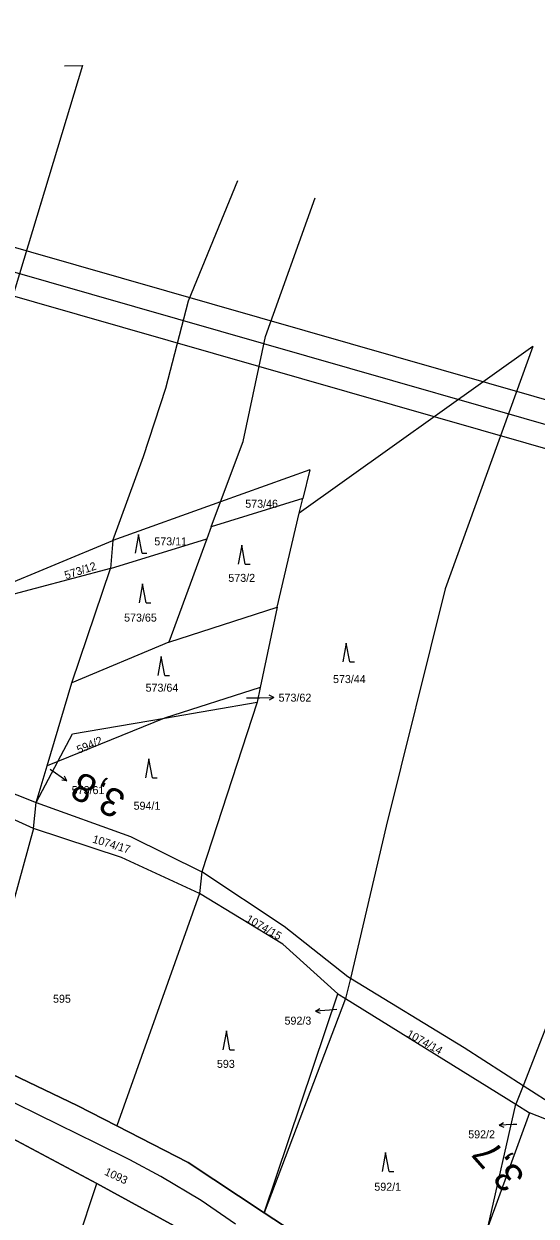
# Model space of a CAD drawing. Extents: x -738085 to -734306, y -1122197 to -1119753.
# Drawn here: x -736902.9 to -736794, y -1121585.1 to -1121331.9 of the extents above; entities that cross this region are included whole.
import ezdxf

# ---------------------------------------------------------------- set-up
doc = ezdxf.new("R2010")
doc.units = 0
for name, color, linetype in [('Hranice parcel', 7, 'Continuous'), ('Parcelní čísla', 7, 'Continuous'), ('Pop  PČ popisy', 7, 'Continuous'), ('SŽDC', 7, 'Continuous'), ('Vrstva 1', 7, 'Continuous'), ('Vrstva 53', 7, 'Continuous'), ('Vrstva 7', 7, 'Continuous'), ('Značky kultur', 7, 'Continuous')]:
    doc.layers.add(name, color=color, linetype=linetype)

msp = doc.modelspace()

# ---------------------------------------------------------------- linework, layer by layer
at = {"layer": 'Hranice parcel'}
for p, q in [((-736794.71, -1121400.41), (-736844.34, -1121435.79)), ((-736842.12, -1121426.59), (-736861.06, -1121433.39)), ((-736842.12, -1121426.59), (-736843.6, -1121432.65)), ((-736861.06, -1121433.39), (-736884.01, -1121441.6)), ((-736843.6, -1121432.65), (-736863.05, -1121438.7)), ((-736863.05, -1121438.7), (-736861.06, -1121433.39)), ((-736844.34, -1121435.79), (-736843.6, -1121432.65)), ((-736849.05, -1121455.75), (-736844.34, -1121435.79)), ((-736863.05, -1121438.7), (-736863.97, -1121441.2)), ((-736884.5, -1121447.55), (-736863.97, -1121441.2)), ((-736863.97, -1121441.2), (-736872.05, -1121463.15)), ((-736922.28, -1121457.48), (-736884.01, -1121441.6)), ((-736884.01, -1121441.6), (-736884.5, -1121447.55)), ((-736884.5, -1121447.55), (-736922.28, -1121457.48)), ((-736892.67, -1121471.82), (-736884.5, -1121447.55)), ((-736872.05, -1121463.15), (-736849.05, -1121455.75)), ((-736849.05, -1121455.75), (-736852.65, -1121472.82)), ((-736872.05, -1121463.15), (-736892.67, -1121471.82)), ((-736897.97, -1121489.45), (-736892.67, -1121471.82)), ((-736852.65, -1121472.82), (-736873.01, -1121479.3)), ((-736852.65, -1121472.82), (-736853.31, -1121475.93)), ((-736873.01, -1121479.3), (-736853.31, -1121475.93)), ((-736853.31, -1121475.93), (-736865.09, -1121511.93)), ((-736873.01, -1121479.3), (-736895.68, -1121488.52)), ((-736921.65, -1121488.79), (-736900.3, -1121497.21)), ((-736900.3, -1121497.21), (-736895.68, -1121488.52)), ((-736895.68, -1121488.52), (-736897.97, -1121489.45)), ((-736900.3, -1121497.21), (-736897.97, -1121489.45)), ((-736900.82, -1121502.75), (-736922.19, -1121493.03)), ((-736900.82, -1121502.75), (-736900.3, -1121497.21)), ((-736900.82, -1121502.75), (-736914.25, -1121550.72)), ((-736865.09, -1121511.93), (-736865.57, -1121516.55)), ((-736865.57, -1121516.55), (-736883.17, -1121565.89)), ((-736833.47, -1121534.61), (-736834.53, -1121538.84)), ((-736833.47, -1121534.61), (-736834.05, -1121534.26)), ((-736851.83, -1121584.35), (-736836.13, -1121537.85)), ((-736834.53, -1121538.84), (-736851.83, -1121584.35)), ((-736836.13, -1121537.85), (-736834.53, -1121538.84)), ((-736834.53, -1121538.84), (-736798.31, -1121561.29)), ((-736796.78, -1121557.37), (-736798.31, -1121561.29)), ((-736916.19, -1121562.83), (-736887.39, -1121578.1)), ((-736804.2, -1121587.16), (-736798.31, -1121561.29)), ((-736798.31, -1121561.29), (-736795.38, -1121563.11)), ((-736795.38, -1121563.11), (-736804.2, -1121587.16)), ((-736883.17, -1121565.89), (-736867.94, -1121573.69)), ((-736867.94, -1121573.69), (-736851.83, -1121584.35)), ((-736920.64, -1121677.71), (-736887.39, -1121578.1)), ((-736887.39, -1121578.1), (-736870.91, -1121587.14))]:
    msp.add_line(p, q, dxfattribs=at)
for points in [[(-736894.23, -1121340.75), (-736890.46, -1121340.68), (-736908.31, -1121399.47), (-736915.28, -1121436.76), (-736922.28, -1121457.48)], [(-736884.01, -1121441.6), (-736877.47, -1121423.75), (-736872.69, -1121409.19), (-736867.93, -1121390.68), (-736857.42, -1121365.14)], [(-736861.06, -1121433.39), (-736856.25, -1121420.58), (-736851.5, -1121398.27), (-736840.95, -1121368.78)], [(-736794.71, -1121400.41), (-736813.35, -1121451.81), (-736825.88, -1121502.26), (-736833.47, -1121534.61)], [(-736759.54, -1121449.86), (-736767.29, -1121474.26), (-736779.34, -1121512.65), (-736796.78, -1121557.37)], [(-736895.68, -1121488.52), (-736892.56, -1121482.65), (-736873.01, -1121479.3)], [(-736900.3, -1121497.21), (-736880.2, -1121504.4), (-736865.09, -1121511.93)], [(-736865.57, -1121516.55), (-736882.16, -1121508.87), (-736900.82, -1121502.75)], [(-736834.05, -1121534.26), (-736847.54, -1121523.54), (-736865.09, -1121511.93)], [(-736836.13, -1121537.85), (-736847.84, -1121527.31), (-736865.57, -1121516.55)], [(-736796.78, -1121557.37), (-736809.3, -1121549.29), (-736833.47, -1121534.61)], [(-736914.25, -1121550.72), (-736891.6, -1121561.57), (-736883.17, -1121565.89)], [(-736779.28, -1121565.27), (-736789.46, -1121562.09), (-736796.78, -1121557.37)], [(-736780.39, -1121568.35), (-736787.24, -1121566.27), (-736795.38, -1121563.11)], [(-736816.01, -1121619.92), (-736826.87, -1121606.1), (-736845.88, -1121588.28), (-736851.83, -1121584.35)]]:
    msp.add_lwpolyline(points, dxfattribs=at)
at = {"layer": 'Pop  PČ popisy'}
for p, q in [((-736855.58, -1121475.01), (-736852.74, -1121474.98)), ((-736852.74, -1121474.98), (-736849.74, -1121474.93)), ((-736849.74, -1121474.93), (-736850.75, -1121474.44)), ((-736849.74, -1121474.93), (-736850.73, -1121475.45)), ((-736897.3, -1121490.14), (-736896.2, -1121490.9)), ((-736896.2, -1121490.9), (-736893.74, -1121492.62)), ((-736893.74, -1121492.62), (-736894.28, -1121491.64)), ((-736893.74, -1121492.62), (-736894.85, -1121492.46)), ((-736840.93, -1121541.56), (-736839.98, -1121540.98)), ((-736837.94, -1121541.3), (-736840.93, -1121541.56)), ((-736840.93, -1121541.56), (-736839.89, -1121541.97)), ((-736836.39, -1121541.17), (-736837.94, -1121541.3)), ((-736801.88, -1121565.71), (-736800.9, -1121565.17)), ((-736798.88, -1121565.6), (-736801.88, -1121565.71)), ((-736801.88, -1121565.71), (-736800.86, -1121566.17)), ((-736798.12, -1121565.57), (-736798.88, -1121565.6))]:
    msp.add_line(p, q, dxfattribs=at)
at = {"layer": 'SŽDC'}
for p, q in [((-736916.19, -1121562.83), (-736887.39, -1121578.1)), ((-736867.94, -1121573.69), (-736883.17, -1121565.89)), ((-736851.83, -1121584.35), (-736867.94, -1121573.69)), ((-736887.39, -1121578.1), (-736870.91, -1121587.14))]:
    msp.add_line(p, q, dxfattribs=at)
for points in [[(-736883.17, -1121565.89), (-736891.6, -1121561.57), (-736914.25, -1121550.72)], [(-736816.01, -1121619.92), (-736826.87, -1121606.1), (-736845.88, -1121588.28), (-736851.83, -1121584.35)]]:
    msp.add_lwpolyline(points, dxfattribs=at)
at = {"layer": 'Vrstva 1'}
for points in [[(-736726.43, -1121430.48), (-737533.93, -1121199.12), (-737615.73, -1121484.62), (-736808.23, -1121715.98)], [(-737530.5, -1121205.3), (-736732.61, -1121433.9), (-736811.65, -1121709.79), (-737609.54, -1121481.19)], [(-736738.79, -1121437.33), (-737330, -1121267.94), (-737406.29, -1121534.23), (-736815.08, -1121703.62)]]:
    msp.add_lwpolyline(points, close=True, dxfattribs=at)
msp.add_lwpolyline([(-736857.9, -1121586.77), (-736865.18, -1121581.77), (-736873.79, -1121576.65), (-736880.36, -1121573.13), (-736887.36, -1121569.62), (-736895.47, -1121565.67), (-736909.09, -1121558.99), (-736915.79, -1121555.68), (-736924.59, -1121551.29), (-736931.47, -1121547.72), (-736939.01, -1121543.72), (-736944.31, -1121540.84), (-736948.04, -1121538.79), (-736964.17, -1121529.72), (-736980.55, -1121520.47)], dxfattribs=at)
at = {"layer": 'Vrstva 53'}
for points in [[(-736870.91, -1121587.14), (-736887.39, -1121578.1), (-736916.19, -1121562.83), (-736926.41, -1121557.42), (-736946.26, -1121546.1), (-736963.67, -1121535.61), (-736980.18, -1121525.56), (-736982.11, -1121524.39), (-736990.76, -1121519.12), (-737010.34, -1121510.73), (-737043.34, -1121491.76), (-737040.45, -1121481.52)], [(-737040.45, -1121481.52), (-737004.89, -1121500.61), (-736987.4, -1121511.36), (-736979.67, -1121517.22), (-736979.36, -1121517.39), (-736977.22, -1121518.54), (-736943.95, -1121536.5), (-736914.25, -1121550.72), (-736891.6, -1121561.57), (-736883.17, -1121565.89), (-736867.94, -1121573.69), (-736851.83, -1121584.35), (-736845.88, -1121588.28)]]:
    msp.add_lwpolyline(points, dxfattribs=at)
at = {"layer": 'Značky kultur'}
for p, q in [((-736878.51, -1121440.28), (-736879.26, -1121444.28)), ((-736877.76, -1121444.28), (-736878.51, -1121440.28)), ((-736856.57, -1121442.58), (-736857.32, -1121446.58)), ((-736855.82, -1121446.58), (-736856.57, -1121442.58)), ((-736877.76, -1121444.28), (-736876.76, -1121444.28)), ((-736855.82, -1121446.58), (-736854.82, -1121446.58)), ((-736877.65, -1121450.8), (-736878.4, -1121454.8)), ((-736876.9, -1121454.8), (-736877.65, -1121450.8)), ((-736876.9, -1121454.8), (-736875.9, -1121454.8)), ((-736834.35, -1121463.37), (-736835.1, -1121467.37)), ((-736833.6, -1121467.37), (-736834.35, -1121463.37)), ((-736873.68, -1121466.21), (-736874.43, -1121470.21)), ((-736872.93, -1121470.21), (-736873.68, -1121466.21)), ((-736833.6, -1121467.37), (-736832.6, -1121467.37)), ((-736872.93, -1121470.21), (-736871.93, -1121470.21)), ((-736876.32, -1121487.96), (-736877.07, -1121491.96)), ((-736875.57, -1121491.96), (-736876.32, -1121487.96)), ((-736875.57, -1121491.96), (-736874.57, -1121491.96)), ((-736859.85, -1121545.72), (-736860.6, -1121549.72)), ((-736859.1, -1121549.72), (-736859.85, -1121545.72)), ((-736859.1, -1121549.72), (-736858.1, -1121549.72)), ((-736825.98, -1121571.57), (-736826.73, -1121575.57)), ((-736825.23, -1121575.57), (-736825.98, -1121571.57)), ((-736825.23, -1121575.57), (-736824.23, -1121575.57))]:
    msp.add_line(p, q, dxfattribs=at)

# ---------------------------------------------------------------- texts
at = {"layer": 'Parcelní čísla'}
for s, p in [('573/46', (-736855.83, -1121434.62)), ('573/11', (-736875.16, -1121442.61)), ('573/2', (-736859.43, -1121450.36)), ('573/65', (-736881.59, -1121458.8)), ('573/44', (-736837.17, -1121471.85)), ('573/64', (-736877.02, -1121473.68)), ('573/62', (-736848.74, -1121475.8)), ('573/61', (-736892.73, -1121495.43)), ('594/1', (-736879.57, -1121498.75)), ('595', (-736896.7, -1121539.74)), ('592/3', (-736847.48, -1121544.39)), ('593', (-736861.85, -1121553.57)), ('592/2', (-736808.43, -1121568.53)), ('592/1', (-736828.39, -1121579.66))]:
    msp.add_text(s, height=1.7, dxfattribs=at).set_placement(p)
for s, rotation, p in [('573/12', 18, (-736893.95, -1121449.84)), ('594/2', 23, (-736891.22, -1121486.88)), ('1074/17', 343, (-736888.45, -1121505.68)), ('1074/15', 330, (-736855.83, -1121522.4)), ('1074/14', 331, (-736821.68, -1121546.84)), ('1093', 335, (-736885.91, -1121576.21))]:
    msp.add_text(s, height=1.7, rotation=rotation, dxfattribs=at).set_placement(p)
at = {"layer": 'Vrstva 7'}
for s, rotation, p in [('3,8', 153.4949, (-736880.84, -1121495.46)), ('3,7', 131.307, (-736796.11, -1121576.55))]:
    msp.add_text(s, height=6, rotation=rotation, dxfattribs=at).set_placement(p)

doc.saveas('drawing.dxf')
